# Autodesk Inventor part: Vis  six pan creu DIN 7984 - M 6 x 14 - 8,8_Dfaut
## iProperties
Created: 2007-07
Part Number: Vis  six pan creu DIN 7984 - M 6 x 14 - 8,8_Dfaut
Document SubType Name: Modeling
Designer: EF
Density: 1 g/cm^3
Author: EF
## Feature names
1. Base1
